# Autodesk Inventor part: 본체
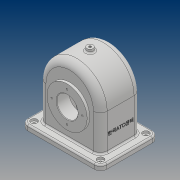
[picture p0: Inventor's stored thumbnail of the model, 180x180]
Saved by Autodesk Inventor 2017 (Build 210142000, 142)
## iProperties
Part Number: 본체
Material: 일반
Document SubType Name: Modeling
Designer: 20
Density: 1 g/cm^3
Appearance: 기본값
Author: 20
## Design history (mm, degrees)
sketch "스케치1"
  geometry: L1 (58, 13)-(58, -65); L2 (58, -65)-(-58, -65); L3 (-58, -65)-(-58, 13); A1 r 58 centre (0, 13) between (58, 13) and (-58, 13); 1 further point
  constraints: 6 end point, 2 point on circle, 2 tangent, 2 vertical, 1 centre point, 1 horizontal
  dimensions: "d0" = 58 distance from line of point (0, 0) L3; "d1" = 116 distance of L1.end L2.end; "d2" = 78 distance from line of A1.centre L2; "d3" = 65 distance from line of L2 point (0, 0); "d4" = 58 radius of A1 (derived)
extrude "돌출1" new body sketch "스케치1" stored distance "d5" = 77; taper "d6" = 0 deg
sketch "스케치2"
  geometry: L1 (58, -65)-(58, 13) reference; L2 (-58, 13)-(-58, -65) reference; L3 (52, -65)-(52, 13); L4 (-52, 13)-(-52, -65); L5 (52, -65)-(-52, -65); L6 (-58, -65)-(58, -65) reference; A1 r 58 centre (0, 13) between (58, 13) and (-58, 13) reference; A2 r 52 centre (0, 13) between (52, 13) and (-52, 13); 1 further point
  constraints: 6 end point, 2 point on circle, 1 centre point, 1 collinear, 1 horizontal, 2 other
  dimensions: "d9" = 6 distance between parallel lines of L1 L3
extrude "돌출2" cut sketch "스케치2" stored distance "d10" = 67; taper "d11" = 0 deg
sketch "스케치3"
  geometry: L1 (-64.83, 0)-(80.389, 0); L2 (33.5, -65)-(-33.5, -65) reference; L3 (33.5, 38)-(48.5, 38); L4 (48.5, 38)-(48.5, 20); L5 (48.5, 20)-(33.5, 20); L6 (33.5, 20)-(33.5, 38); L7 (33.5, 13)-(33.5, 65) reference; L8 (-38.5, 71)-(-38.5, 13) reference; L9 (-33.5, 65)-(-33.5, 13) reference; L10 (-33.5, 39.747)-(-19.5, 28); L11 (-19.5, 28)-(-19.5, 20); L12 (-19.5, 20)-(-43.5, 20); L13 (-43.5, 20)-(-43.5, 38); L14 (-43.5, 38)-(-38.5, 38); L15 (-38.5, 38)-(-38.5, 39.747); L16 (-38.5, 39.747)-(-33.5, 39.747); 1 further point
  constraints: 24 end point, 5 horizontal, 2 collinear, 2 parallel, 2 vertical, 1 perpendicular, 1 point on line
  dimensions: "d12" = 65 distance between parallel lines of L1 L2; "d14" = 40 diameter of L5 L1; "d15" = 76 diameter of L3 L1; "d16" = 87 distance between parallel lines of L4 L8; "d22" = 5 distance between parallel lines of L9 L8 (derived); "d23" = 15 distance of L4.end L5.end (derived); "d24" = 40 diameter of L12 L1; "d25" = 56 diameter of L10.end L1; "d26" = 76 diameter of L14 L1; "d27" = 24 distance of L11.end L12.end; "d29" = 5 distance between parallel lines of L8 L13; "d30" = 50 deg angle of L11 L10
revolve "회전1" sketch "스케치3" stored, may be unused: angle "d31" = 90 deg
sketch "스케치4"
  geometry: C1 r 20 at (0, 0) reference; C2 r 20 at (0, 0); 1 further point
  constraints: 1 centre point, 1 coincident
  dimensions: "d32" = 40 diameter of C2
extrude "돌출3" cut sketch "스케치4" stored distance "d33" = 67; taper "d34" = 0 deg
sketch "스케치5"
  geometry: L1 (-17, 16.5)-(133, 16.5); L2 (133, 16.5)-(133, -93.5); L3 (133, -93.5)-(-17, -93.5); L4 (-17, -93.5)-(-17, 16.5); L5 (-17, 16.5)-(133, -93.5); L6 (133, 16.5)-(-17, -93.5); L7 (6, -72)-(110, -72) reference; L8 (110, -5)-(6, -5); L9 (6, -5)-(6, -72); L10 (6, -72)-(110, -72); L11 (110, -72)-(110, -5); L12 (110, -5)-(6, -72); L13 (6, -5)-(110, -72); 2 further points
  constraints: 24 end point, 6 midpoint, 4 parallel, 2 horizontal, 2 perpendicular
  dimensions: "d35" = 150 distance of L2.end L3.end; "d36" = 110 distance of L1.end L2.end
extrude "돌출4" join sketch "스케치5" distance "d37" = 10; taper "d38" = 0 deg
node "작업 평면1"
sketch "스케치6"
  geometry: C1 r 6 at (75, -55); 1 further point
  constraints: 1 centre point, 1 coincident
  dimensions: "d40" = 12 diameter of C1
extrude "돌출5" join sketch "스케치6" stored distance "d41" = 10; taper "d42" = 0 deg
hole "구멍1" diameter "d45" = 4.459; stored, may be unused: countersink angle "d49" = 90 deg, drill point angle "d51" = 118 deg; dims "d43" = 10, "d44" = 10, "d46" = 10, "d47" = 4, "d48" = 2, "d50" = 50
fillet "모깎기1" dims "d52" = 12
sketch "스케치8"
  geometry: A1 r 12 centre (-121, 4.5) between (-121, 16.5) and (-133, 4.5) reference; 2 further points
  constraints: 1 coincident
hole "구멍2" sketch "스케치8" at (-121, 4.5) diameter "d53" = 5; stored, may be unused: countersink angle "d57" = 90 deg, drill point angle "d59" = 118 deg; dims "d54" = 10, "d55" = 12, "d56" = 4, "d58" = 50
fillet "모깎기2" dims "d66" = 13
fillet "모깎기3" dims "d67" = 8
fillet "모깎기5" dims "d69" = 3
chamfer "모따기1" distance "d70" = 1; stored, may be unused: second distance "d71" = 2, angle "d72" = 45 deg
sketch "스케치9"
  geometry: 2 further points
  constraints: 1 vertical alignment
  dimensions: "d73" = 29 distance of point (0, 0) point (0, 29)
hole "구멍3" sketch "스케치9" at (0, 29) diameter "d74" = 3.242; stored, may be unused: countersink angle "d78" = 90 deg, drill point angle "d80" = 118 deg; dims "d75" = 8, "d76" = 12, "d77" = 4, "d79" = 10
sketch "스케치10"
  geometry: C1 r 1.621 at (0, -29) reference; 2 further points
  constraints: 1 coincident
hole "구멍4" sketch "스케치10" at (0, -29) diameter "d84" = 3.242; stored, may be unused: countersink angle "d88" = 90 deg, drill point angle "d90" = 118 deg; dims "d85" = 8, "d86" = 12, "d87" = 4, "d89" = 10
fillet "모깎기6" dims "d94" = 3
sketch "스케치11"
  geometry: L1 (78, -17.5)-(78, 68.5) reference; L2 (0, -13)-(65, -13) reference; 2 further points
  constraints: 1 other
  dimensions: "d95" = 40 distance from line of L1 point (38, 25.5); "d96" = 38.5 distance from line of point (38, 25.5) L2
feature "엠보싱1" sketch "스케치11" dims "d12" = 65, "d14" = 40, "d15" = 76, "d16" = 87, "d23" = 15 (derived), "d24" = 40, "d25" = 56, "d26" = 76, "d27" = 24, "d29" = 5, "d30" = 50 deg, "d97" = 0.5, "d98" = 0
feature "면 기울기1" dims angle "d99" = 5 deg
fillet "모깎기7" dims "d100" = 3
node "솔리드1"
pattern_linear "직사각형 패턴1" dims "d62" = 126, "d65" = 86
pattern_circular "원형 패턴1" dims angle "d82" = 360 deg
pattern_circular "원형 패턴2" dims angle "d92" = 360 deg
other parameters: "d39" = -142
